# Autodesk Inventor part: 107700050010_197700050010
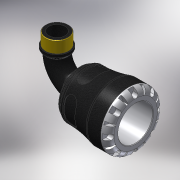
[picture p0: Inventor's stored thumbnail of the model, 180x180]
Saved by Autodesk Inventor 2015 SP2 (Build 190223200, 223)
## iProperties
Created: 2016-12
Part Number: 107700050010_197700050010
Material: PVC-Piping
Description: PLASSON 90° ELBOW WITH MALE INTEGRAL BRASS 50X1" SERIES 1
Document SubType Name: Modeling
Designer: KIM
Mass: 664.223 g
Surface Area: 733.008 cm^2
Volume: 474.445 cm^3
Density: 1.4 g/cm^3
Appearance: Black Cast
Author: KIM
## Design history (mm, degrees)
derived "1077.ipt"
feature "Solid1::1077.ipt"
tag "TaggingFeature1"
body "Solid1"
other parameters: "d1" = 33.18, "d3" = 62.5, "d4" = 85, "d8" = 72.25, "d13" = 9, "d14" = 9, "d15" = 0, "d17" = 360 deg, "d19" = 8 deg, "d20" = 1, "d21" = 1, "d22" = 8 deg, "d24" = 0, "d26" = 360 deg, "d33" = 8.5, "d43" = 66.3, "d51" = 0.85, "d54" = 17.5, "d55" = 11, "d57" = 17.64, "d58" = 0, "d74" = 0, "d78" = 79, "d82" = 1, "d115" = 360 deg, "d207" = 90 deg, "d228" = 14.875, "d247" = 1.7, "d248" = 4.74, "d268" = 39.7375, "d269" = 4.74, "d270" = 116, "d276" = 33.249, "d277" = 19, "d278" = 36.5739, "d279" = 62, "d280" = 24.7, "d281" = 4.98735, "d283" = 29.9241, "d286" = 0, "d287" = 0, "d288" = 23.2743, "d290" = 18.18795, "d292" = 30 deg, "d294" = 3.3249, "d296" = 30 deg, "E_" = 85, "l_" = 79, "A_" = 116, "A_1" = 62, "l_2" = 19, "R_" = 33.249, "d9" = 11.25, "d11" = 85, "d12" = 62.5, "d289" = 23.2743
